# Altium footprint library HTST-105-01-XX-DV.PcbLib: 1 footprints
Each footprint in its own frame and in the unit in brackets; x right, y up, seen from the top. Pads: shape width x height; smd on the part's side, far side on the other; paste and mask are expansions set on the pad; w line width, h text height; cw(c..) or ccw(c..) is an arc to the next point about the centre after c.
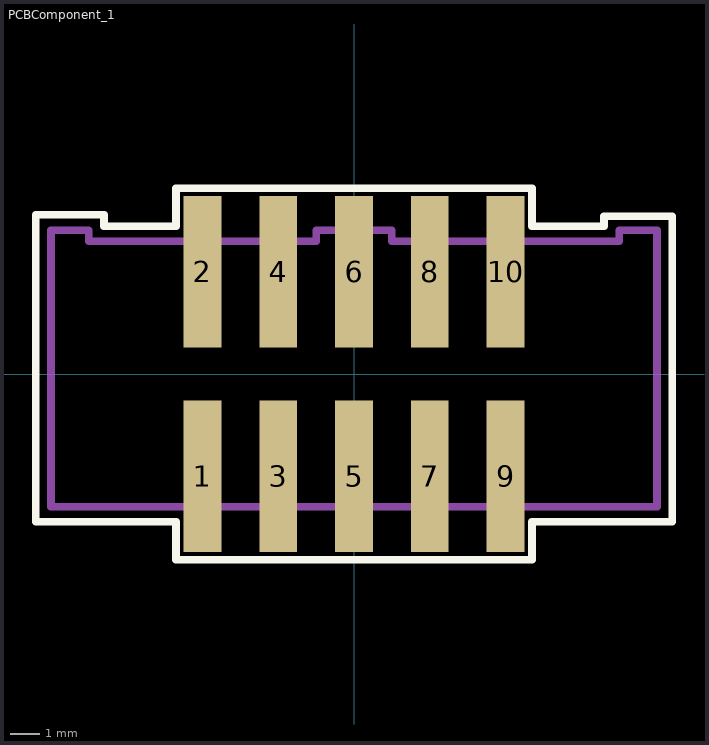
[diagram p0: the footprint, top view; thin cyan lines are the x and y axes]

## PCBComponent_1 [mil]
pads (10):
  rect 50x200 smd mask+2: 1(-200,-135) 2(-200,135) 3(-100,-135) 4(-100,135) 5(0,-135) 6(0,135) 7(100,-135) 8(100,135) 9(200,-135) 10(200,135)
Top Overlay:
  lines w10: -420,-195 -235,-195 -235,-245 235,-245 235,-195 420,-195 420,208.48 330,208.48 330,195 235,195 235,245 -235,245 -235,195 -330,195 -330,210 -420,210 -420,-195
Mechanical 1:
  lines w10: -400,-175 400,-175 400,190 350,190 350,175 50,175 50,190 -50,190 -50,175 -350,175 -350,190 -400,190 -400,-175
  text "J1" at -17.57,-18 h30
